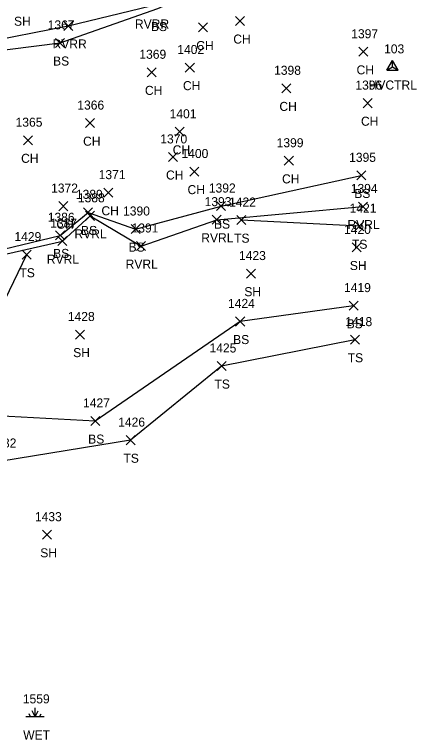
# Model space of a CAD drawing. Extents: x 1678553 to 1680768, y 787260 to 792325.
# Drawn here: x 1678737.4 to 1678826.4, y 787427.7 to 787588.2 of the extents above; entities that cross this region are included whole.
import ezdxf

# ---------------------------------------------------------------- set-up
doc = ezdxf.new("R2010")
doc.units = 0
for name, color, linetype in [('C_A', 7, 'Continuous'), ('C_I', 7, 'Continuous'), ('CPSM', 7, 'Continuous'), ('L_A', 7, 'Continuous'), ('L_I', 7, 'Continuous'), ('L_TIC', 7, 'Continuous'), ('LAWE', 7, 'Continuous'), ('LELB', 7, 'Continuous'), ('LWET', 7, 'Continuous')]:
    doc.layers.add(name, color=color, linetype=linetype)

msp = doc.modelspace()

# ---------------------------------------------------------------- linework, layer by layer
at = {"layer": 'CPSM'}
for p, q in [((1678819.87, 787575.91), (1678821.12, 787578.07)), ((1678822.37, 787575.91), (1678821.12, 787578.07)), ((1678821.12, 787576.63), (1678821.12, 787578.07)), ((1678819.87, 787575.91), (1678821.12, 787576.63)), ((1678821.12, 787576.63), (1678821.12, 787576.63)), ((1678821.12, 787576.63), (1678822.37, 787575.91)), ((1678819.87, 787575.91), (1678822.37, 787575.91))]:
    msp.add_line(p, q, dxfattribs=at)
at = {"layer": 'L_TIC'}
for points in [[(1678786.36, 787585.8), (1678788.36, 787587.8)], [(1678788.36, 787585.8), (1678786.36, 787587.8)], [(1678748.3, 787584.72), (1678750.3, 787586.72)], [(1678750.3, 787584.72), (1678748.3, 787586.72)], [(1678778.15, 787584.37), (1678780.15, 787586.37)], [(1678780.15, 787584.37), (1678778.15, 787586.37)], [(1678746.48, 787580.94), (1678748.48, 787582.94)], [(1678748.48, 787580.94), (1678746.48, 787582.94)], [(1678813.66, 787578.98), (1678815.66, 787580.98)], [(1678815.66, 787578.98), (1678813.66, 787580.98)], [(1678766.79, 787574.44), (1678768.79, 787576.44)], [(1678768.79, 787574.44), (1678766.79, 787576.44)], [(1678775.22, 787575.49), (1678777.22, 787577.49)], [(1678777.22, 787575.49), (1678775.22, 787577.49)], [(1678796.57, 787570.89), (1678798.57, 787572.89)], [(1678798.57, 787570.89), (1678796.57, 787572.89)], [(1678814.64, 787567.61), (1678816.64, 787569.61)], [(1678816.64, 787567.61), (1678814.64, 787569.61)], [(1678753.1, 787563.19), (1678755.1, 787565.19)], [(1678755.1, 787563.19), (1678753.1, 787565.19)], [(1678772.94, 787561.27), (1678774.94, 787563.27)], [(1678774.94, 787561.27), (1678772.94, 787563.27)], [(1678739.37, 787559.4), (1678741.37, 787561.4)], [(1678741.37, 787559.4), (1678739.37, 787561.4)], [(1678771.46, 787555.7), (1678773.46, 787557.7)], [(1678773.46, 787555.7), (1678771.46, 787557.7)], [(1678797.15, 787554.85), (1678799.15, 787556.85)], [(1678799.15, 787554.85), (1678797.15, 787556.85)], [(1678776.22, 787552.47), (1678778.22, 787554.47)], [(1678778.22, 787552.47), (1678776.22, 787554.47)], [(1678813.2, 787551.62), (1678815.2, 787553.62)], [(1678815.2, 787551.62), (1678813.2, 787553.62)], [(1678757.15, 787547.79), (1678759.15, 787549.79)], [(1678759.15, 787547.79), (1678757.15, 787549.79)], [(1678747.18, 787544.81), (1678749.18, 787546.81)], [(1678749.18, 787544.81), (1678747.18, 787546.81)], [(1678782.13, 787544.83), (1678784.13, 787546.83)], [(1678784.13, 787544.83), (1678782.13, 787546.83)], [(1678813.56, 787544.73), (1678815.56, 787546.73)], [(1678815.56, 787544.73), (1678813.56, 787546.73)], [(1678752.68, 787543.43), (1678754.68, 787545.43)], [(1678754.68, 787543.43), (1678752.68, 787545.43)], [(1678753.11, 787542.67), (1678755.11, 787544.67)], [(1678755.11, 787542.67), (1678753.11, 787544.67)], [(1678781.18, 787541.81), (1678783.18, 787543.81)], [(1678783.18, 787541.81), (1678781.18, 787543.81)], [(1678786.61, 787541.72), (1678788.61, 787543.72)], [(1678788.61, 787541.72), (1678786.61, 787543.72)], [(1678763.21, 787539.74), (1678765.21, 787541.74)], [(1678765.21, 787539.74), (1678763.21, 787541.74)], [(1678812.73, 787540.38), (1678814.73, 787542.38)], [(1678814.73, 787540.38), (1678812.73, 787542.38)], [(1678746.5, 787538.35), (1678748.5, 787540.35)], [(1678748.5, 787538.35), (1678746.5, 787540.35)], [(1678746.99, 787537.07), (1678748.99, 787539.07)], [(1678748.99, 787537.07), (1678746.99, 787539.07)], [(1678764.43, 787535.98), (1678766.43, 787537.98)], [(1678766.43, 787535.98), (1678764.43, 787537.98)], [(1678812.16, 787535.67), (1678814.16, 787537.67)], [(1678814.16, 787535.67), (1678812.16, 787537.67)], [(1678739.07, 787534.07), (1678741.07, 787536.07)], [(1678741.07, 787534.07), (1678739.07, 787536.07)], [(1678788.8, 787529.88), (1678790.8, 787531.88)], [(1678790.8, 787529.88), (1678788.8, 787531.88)], [(1678811.5, 787522.78), (1678813.5, 787524.78)], [(1678813.5, 787522.78), (1678811.5, 787524.78)], [(1678786.37, 787519.28), (1678788.37, 787521.28)], [(1678788.37, 787519.28), (1678786.37, 787521.28)], [(1678750.9, 787516.39), (1678752.9, 787518.39)], [(1678752.9, 787516.39), (1678750.9, 787518.39)], [(1678811.78, 787515.25), (1678813.78, 787517.25)], [(1678813.78, 787515.25), (1678811.78, 787517.25)], [(1678782.27, 787509.42), (1678784.27, 787511.42)], [(1678784.27, 787509.42), (1678782.27, 787511.42)], [(1678754.26, 787497.25), (1678756.26, 787499.25)], [(1678756.26, 787497.25), (1678754.26, 787499.25)], [(1678762.1, 787493.01), (1678764.1, 787495.01)], [(1678764.1, 787493.01), (1678762.1, 787495.01)], [(1678743.6, 787472.07), (1678745.6, 787474.07)], [(1678745.6, 787472.07), (1678743.6, 787474.07)]]:
    msp.add_lwpolyline(points, dxfattribs=at)
at = {"layer": 'LAWE'}
for points in [[(1678722.67, 787582.69), (1678729.64, 787581.87), (1678749.3, 787585.72), (1678767.55, 787590.14), (1678784.53, 787599.95), (1678818.4, 787617.01)], [(1678710.45, 787522.31), (1678712.95, 787530.78), (1678730.73, 787534.14), (1678747.99, 787538.07), (1678754.11, 787543.67), (1678765.43, 787536.98), (1678782.18, 787542.81), (1678814.56, 787545.73)]]:
    msp.add_lwpolyline(points, dxfattribs=at)
at = {"layer": 'LELB'}
for points in [[(1678720.9, 787579.97), (1678730.54, 787579.83), (1678747.48, 787581.94), (1678769.16, 787589.57), (1678788.93, 787598.35), (1678821.69, 787613.87)], [(1678709.31, 787522.85), (1678712, 787531.65), (1678730.58, 787535.28), (1678747.5, 787539.35), (1678753.68, 787544.43), (1678764.21, 787540.74), (1678783.13, 787545.83), (1678814.2, 787552.62)], [(1678813.73, 787541.38), (1678787.61, 787542.72)], [(1678740.07, 787535.07), (1678729.41, 787513.1), (1678730.57, 787499.54), (1678734.56, 787489.38)], [(1678812.5, 787523.78), (1678787.37, 787520.28), (1678755.26, 787498.25), (1678730.57, 787499.54), (1678731.75, 787490.21)], [(1678812.78, 787516.25), (1678783.27, 787510.42), (1678763.1, 787494.01), (1678734.56, 787489.38), (1678724.29, 787475.38)]]:
    msp.add_lwpolyline(points, dxfattribs=at)
at = {"layer": 'LWET'}
for p, q in [((1678741.93, 787432.74), (1678741.27, 787434.08)), ((1678741.93, 787432.74), (1678741.93, 787434.74)), ((1678741.93, 787432.74), (1678742.6, 787434.08)), ((1678743.93, 787432.74), (1678739.93, 787432.74)), ((1678740.93, 787432.74), (1678740.6, 787433.41)), ((1678742.93, 787432.74), (1678743.27, 787433.41))]:
    msp.add_line(p, q, dxfattribs=at)

# ---------------------------------------------------------------- texts
at = {"layer": 'C_A'}
msp.add_text('HVCTRL', height=2, dxfattribs=at).set_placement((1678815.82, 787571.63))
at = {"layer": 'C_I'}
msp.add_text('103', height=2, dxfattribs=at).set_placement((1678819.25, 787579.63))
at = {"layer": 'L_A'}
for s, p in [('SH', (1678737.28, 787585.75)), ('RVRR', (1678764.06, 787585.14)), ('BS', (1678767.6, 787584.57)), ('RVRR', (1678745.82, 787580.72)), ('CH', (1678785.85, 787581.8)), ('CH', (1678777.64, 787580.37)), ('BS', (1678745.93, 787576.94)), ('CH', (1678813.15, 787574.98)), ('CH', (1678774.7, 787571.49)), ('CH', (1678766.28, 787570.44)), ('CH', (1678796.06, 787566.89)), ('CH', (1678814.13, 787563.61)), ('CH', (1678752.58, 787559.19)), ('CH', (1678772.43, 787557.27)), ('CH', (1678738.85, 787555.4)), ('CH', (1678770.95, 787551.7)), ('CH', (1678796.64, 787550.85)), ('CH', (1678775.71, 787548.47)), ('BS', (1678812.64, 787547.62)), ('CH', (1678756.64, 787543.79)), ('CH', (1678746.67, 787540.81)), ('BS', (1678781.57, 787540.83)), ('RVRL', (1678811.12, 787540.73)), ('BS', (1678752.12, 787539.43)), ('RVRL', (1678750.67, 787538.67)), ('RVRL', (1678778.75, 787537.81)), ('TS', (1678786.02, 787537.72)), ('BS', (1678762.65, 787535.74)), ('TS', (1678812.14, 787536.38)), ('BS', (1678745.94, 787534.35)), ('RVRL', (1678744.55, 787533.07)), ('RVRL', (1678762, 787531.98)), ('SH', (1678811.65, 787531.67)), ('TS', (1678738.48, 787530.07)), ('SH', (1678788.29, 787525.88)), ('BS', (1678810.95, 787518.78)), ('BS', (1678785.81, 787515.28)), ('SH', (1678750.38, 787512.39)), ('TS', (1678811.19, 787511.25)), ('TS', (1678781.68, 787505.42)), ('BS', (1678753.7, 787493.25)), ('TS', (1678761.51, 787489.01)), ('SH', (1678743.09, 787468.07)), ('WET', (1678739.31, 787427.74))]:
    msp.add_text(s, height=2, dxfattribs=at).set_placement(p)
at = {"layer": 'L_I'}
for s, p in [('1367', (1678744.74, 787584.94)), ('1397', (1678811.97, 787582.98)), ('1402', (1678773.44, 787579.49)), ('1369', (1678765.04, 787578.44)), ('1398', (1678794.88, 787574.89)), ('1396', (1678812.89, 787571.61)), ('1366', (1678751.3, 787567.19)), ('1401', (1678771.74, 787565.27)), ('1365', (1678737.63, 787563.4)), ('1370', (1678769.68, 787559.7)), ('1399', (1678795.45, 787558.85)), ('1400', (1678774.37, 787556.47)), ('1395', (1678811.5, 787555.62)), ('1371', (1678756.03, 787551.79)), ('1372', (1678745.49, 787548.81)), ('1392', (1678780.43, 787548.83)), ('1394', (1678811.86, 787548.73)), ('1389', (1678750.98, 787547.43)), ('1388', (1678751.42, 787546.67)), ('1393', (1678779.49, 787545.81)), ('1422', (1678784.91, 787545.72)), ('1421', (1678811.61, 787544.38)), ('1386', (1678744.75, 787542.35)), ('1390', (1678761.43, 787543.74)), ('1387', (1678745.29, 787541.07)), ('1391', (1678763.31, 787539.98)), ('1420', (1678810.38, 787539.67)), ('1429', (1678737.37, 787538.07)), ('1423', (1678787.11, 787533.88)), ('1419', (1678810.37, 787526.78)), ('1424', (1678784.67, 787523.28)), ('1428', (1678749.2, 787520.39)), ('1418', (1678810.66, 787519.25)), ('1425', (1678780.58, 787513.42)), ('1427', (1678752.56, 787501.25)), ('1426', (1678760.35, 787497.01)), ('1432', (1678731.86, 787492.38)), ('1432', (1678731.86, 787492.38)), ('1433', (1678741.91, 787476.07)), ('1559', (1678739.23, 787435.74))]:
    msp.add_text(s, height=2, dxfattribs=at).set_placement(p)

doc.saveas('drawing.dxf')
